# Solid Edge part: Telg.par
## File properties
Author: jaanm
Template: Ansi Metric part.par
Last saved by: jaanm
Revision: 5
Application: Solid Edge
Accuracy: 0,990
Face Style: Model Default
Fill Style: Normal
Coef. of Thermal Exp: 0.0
Thermal Conductivity: 0.0
Specific Heat: 0.0
Modulus of Elasticity: 0.0
Poisson's Ratio: 0.0
Yield Stress: 0.0
Ultimate Stress: 0.0
Elongation: 0.0
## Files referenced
..\Lendavkaru.asm
C:\Users\jaanm\Google Drive\Ained2016\3dmodel\Lendav käru\Velg.var1.par
ru\Lendavkaru.asm
ru\Velg.var1.par
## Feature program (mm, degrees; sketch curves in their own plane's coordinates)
sketch for "ExtrudedProtrusion_2" plane through (0, 100, 0) normal (0, -1, 0) x-axis (1, 0, 0)
  circle centre (0, 0) radius 45
extrude "ExtrudedProtrusion_2" add finite 100 along +normal
sketch for "ExtrudedProtrusion_3" plane through (0, 0, 0) normal (0, -1, 0) x-axis (0, 0, -1)
  circle centre (0, 0) radius 25
extrude "ExtrudedProtrusion_3" add finite 800 along +normal
multibody boolean "unnamed MultibodyBoolean 1"
sketch for "unnamed Cutout 1" #1 plane through (0, 100, 0) normal (0, 1, 0) x-axis (-1, 0, 0)
  circle centre (0, 0) radius 40.9424
sketch for "unnamed Cutout 1" #2 plane through (0, 100, 0) normal (0, 1, 0) x-axis (-1, 0, 0)
  circle centre (0, 0) radius 48.411
extrude "unnamed Cutout 1" cut to key point along -normal
sketch for "ExtrudedProtrusion_6" #1 plane through (-23.4552, 100, 18.7046) normal (0, 1, 0) x-axis (0, 0, -1)
  circle centre (-0.0372, -0.0186) radius 10.0415
sketch for "ExtrudedProtrusion_6" #2 plane through (-23.4552, 100, 18.7046) normal (0, 1, 0) x-axis (0, 0, -1)
  circle centre (0, 0) radius 3.5
extrude "ExtrudedProtrusion_6" add finite 5 along +normal
pattern "Pattern_1" of "ExtrudedProtrusion_6" along a curve  XDirCount = 7; XDirSpacing = 13.464 mm
extrude "unnamed Protrusion 1" add finite 5
extrude "unnamed Protrusion 2" add finite 5
extrude "unnamed Protrusion 3" add finite 5
extrude "unnamed Protrusion 4" add finite 5
extrude "unnamed Protrusion 5" add finite 5
extrude "unnamed Protrusion 6" add finite 5
mirror "unnamed Mirror 1" of "ExtrudedProtrusion_6", "unnamed Cutout 1", "unnamed MultibodyBoolean 1", "ExtrudedProtrusion_2" about plane through (0, -400, 0) normal (0, -1, 0)
extrude "unnamed Protrusion 7" add finite 100
multibody boolean "unnamed MultibodyBoolean 2"
extrude "unnamed Cutout 2" cut finite 49.9612
extrude "unnamed Protrusion 8" add finite 5
extrude "unnamed Protrusion 9" add finite 5
extrude "unnamed Protrusion 10" add finite 5
extrude "unnamed Protrusion 11" add finite 5
extrude "unnamed Protrusion 12" add finite 5
extrude "unnamed Protrusion 13" add finite 5
extrude "unnamed Protrusion 14" add finite 5
multibody boolean "unnamed MultibodyBoolean 3"
sketch for "ExtrudedProtrusion_45" #1 plane through (0, 0, 0) normal (1, 0, 0) x-axis (0, 1, 0)
  line (-561.5073, -20) -> (-561.5073, 20)
  line (-561.5073, 20) -> (-601.5073, 20)
  line (-601.5073, 20) -> (-601.5073, -20)
  line (-601.5073, -20) -> (-561.5073, -20)
sketch for "ExtrudedProtrusion_45" #2 plane through (0, 0, 0) normal (1, 0, 0) x-axis (0, 1, 0)
  line (-238.4927, -20) -> (-238.4927, 20)
  line (-238.4927, 20) -> (-198.4927, 20)
  line (-198.4927, 20) -> (-198.4927, -20)
  line (-198.4927, -20) -> (-238.4927, -20)
extrude "ExtrudedProtrusion_45" add finite 50 along +normal
fillet "Round_1" radius 10
swept protrusion "SweptProtrusion_1"
mirror "unnamed Mirror 2" of "SweptProtrusion_1" about plane through (0, -400, 0) normal (0, -1, 0)
swept protrusion "unnamed SweptProtrusion 1"
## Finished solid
Body 1: solid body, 77 faces, 180 edges, 89 vertices.
  Faces by surface: cylinder 40, plane 24, torus 12, cone 1
  Edges by curve: circle 81, line 68, intersection 30, curve on surface 1
Body 2: solid body, 77 faces, 180 edges, 89 vertices.
  Faces by surface: cylinder 40, plane 24, torus 12, cone 1
  Edges by curve: circle 81, line 68, intersection 30, curve on surface 1
Body 3: solid body, 149 faces, 192 edges, 54 vertices.
  Faces by surface: plane 74, cylinder 67, spline 4, torus 4
  Edges by curve: circle 132, intersection 28, line 28, curve on surface 4
Bounding box of the edges (mm; curved faces can reach further): 611.117 x 1010.000 x 1184.312, from (-125, -905, -1059.312) to (486.117, 105, 125).
Cylindrical faces by radius (mm): R3.5 x14, R6.5 x28, R10 x54, R10.0415 x14, R15 x4, R25 x1, R44.8943 x18, R45 x2, R79.6098 x10, R105 x2
Conical faces (half-angle, radius in mm at the cone's reference point): 0 deg R79.6098 x2
Toroidal faces (ring radius, tube radius in mm): R35 r10 x4, R56.1241 r23.4857 x6, R89.6098 r10 x10, R99.375 r25.625 x4, R102.3049 r23.9455 x2, R106.5839 r6 x2
Planar faces by outward normal: +x 2, +y 47, +z 4, -y 47, -z 2, oblique 20
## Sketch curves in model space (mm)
line (0, -561.5073, -20) -> (0, -561.5073, 20)
line (0, -561.5073, 20) -> (0, -601.5073, 20)
line (0, -601.5073, 20) -> (0, -601.5073, -20)
line (0, -601.5073, -20) -> (0, -561.5073, -20)
line (0, -238.4927, -20) -> (0, -238.4927, 20)
line (0, -238.4927, 20) -> (0, -198.4927, 20)
line (0, -198.4927, 20) -> (0, -198.4927, -20)
line (0, -198.4927, -20) -> (0, -238.4927, -20)
circle centre (0, -581.5073, 0) radius 20
circle centre (0, -218.4927, 0) radius 20
line (396.9616, -581.5073, -661.9159) -> (466.4208, -581.5073, -1055.839)
arc centre (200, -581.5073, -696.6455) radius 200 from (200, -581.5073, -496.6455) through (328.5575, -581.5073, -543.4367) to (396.9616, -581.5073, -661.9159)
line (0, -581.5073, 0) -> (0, -581.5073, -133.6834)
arc centre (-130.0388, -581.5073, -133.6834) radius 130.0388 from (0, -581.5073, -133.6834) through (-21.2808, -581.5073, -204.9701) to (-78.1581, -581.5073, -252.9247)
arc centre (-78.1581, -581.5073, -302.7502) radius 49.8254 from (-78.1581, -581.5073, -352.5756) through (-127.9616, -581.5073, -301.2737) to (-78.1581, -581.5073, -252.9247)
arc centre (-78.1581, -581.5073, -493.1326) radius 140.5571 from (-78.1581, -581.5073, -352.5756) through (-13.5139, -581.5073, -368.3231) to (36.6452, -581.5073, -412.0371)
arc centre (200, -581.5073, -296.6455) radius 200 from (36.6452, -581.5073, -412.0371) through (108.0172, -581.5073, -474.2382) to (200, -581.5073, -496.6455)
circle centre (-23.4366, 100, 18.7418) radius 10.0415
circle centre (-23.4552, 100, 18.7046) radius 3.5
circle centre (0, 100, 0) radius 48.411
circle centre (0, 100, 0) radius 40.9424
circle centre (0, 0, 0) radius 25
circle centre (0, 100, 0) radius 45
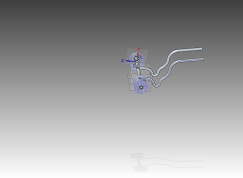
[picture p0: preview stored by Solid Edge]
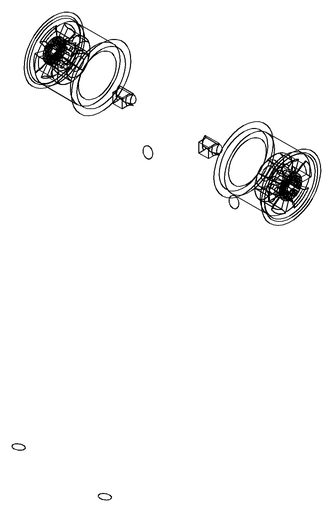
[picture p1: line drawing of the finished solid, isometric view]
